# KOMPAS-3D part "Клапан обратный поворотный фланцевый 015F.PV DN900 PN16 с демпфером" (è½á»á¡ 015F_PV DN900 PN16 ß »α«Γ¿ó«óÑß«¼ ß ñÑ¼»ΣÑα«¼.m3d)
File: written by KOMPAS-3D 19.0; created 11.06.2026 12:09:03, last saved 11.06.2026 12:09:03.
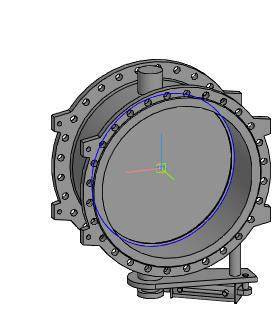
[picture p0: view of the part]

Document properties: Автор: Энергия; Полное имя файла: Z:\3.Личные\kachalov\001_3d для проектировщиков\5.5 Тип 015F.PV Клапан обратный поворотный с двумя эксцентриками\_stp_Клапан 015F.PV DN300-DN1200 с противовесом с демпфером\Клапан 015F_PV DN900 PN16 с противовесом с демпфером.m3d

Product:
- Part/product: Клапан обратный поворотный фланцевый 015F.PV DN900 PN16 с демпфером

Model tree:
1. Операция без истории:1
2. Сплайн:1
     Координата Y = 30; Координата Z = 450; Вес = 1; Координата X = 900; Координата Y = 148.487; Координата Z = 450; Вес = 0.333333; Координата X = 900; Координата Y = 148.487; Координата Z = -450; Вес = 0.333333; Координата Y = 30; Координата Z = -450; Вес = 1; Координата X = -900; Координата Y = -88.4872; Координата Z = -450; Вес = 0.333333; Координата X = -900; Координата Y = -88.4872; Координата Z = 450; Вес = 0.333333; Порядок = 4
